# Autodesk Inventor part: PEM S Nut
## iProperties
Author: John A. Hunter
Shininess: 64.0
Angle Display Precision: 2
Document Length Units: 11272
Document Angle Units: 11286
Document Time Units: 11279
Document Mass Units: 11290
Document Length Units Precision: 3
Document Angle Units Precision: 2
Compacted: True
PropertySet Name: _Private Model Information
Created: 2002-08
Part Number: PEM S Nut
Material: Steel, High Strength Low Alloy
Description: S-256-0
Document SubType Name: Modeling
Designer: John A. Hunter
Control State: 0
Master: False
Checked Out: False
PropertySet Name: Design Tracking Control
Density: 0.0
Volumn: 0.0
Area: 0.0
PropertySet Name: Model Information
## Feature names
1. Extrusion1
2. Extrusion2
3. Hole1
